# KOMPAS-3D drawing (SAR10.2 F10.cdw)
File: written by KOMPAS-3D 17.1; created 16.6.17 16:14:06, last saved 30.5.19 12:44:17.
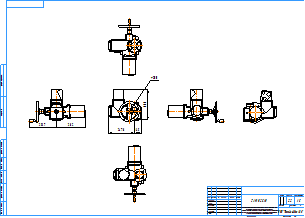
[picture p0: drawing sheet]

Sheet 1: A2, landscape

Title block, sheet 1: name: SAR10.2 F10; material: Сталь 20  ГОСТ 1050-88; mass: 22; sheets: 1; sheet format: A2; stored path: \\adlc.lan\data\АДЛ_ПКД\3D-модели\Поставщики\Сервоприводы AUMA\Электроприводы серии SA\KOMPAS 2D\SA 10.2 F10.cdw

Views: Спереди 1, Проекционный вид 3, Проекционный вид 4, Проекционный вид 6, Проекционный вид 5, Проекционный вид 2
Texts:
  Klimkovich
  ADL
  Рама для чертежей
  Лит-Масса-Масштаб
  Материал-Предприятие
  Масштаб
  Изм.
  Лист
  № докум.
  Подп.
  Дата
  Лит.
  Разраб.
  Пров.
  Т.контр.
  Листов
  Внимание! Данный продукт является объектом авторского права ООО «Торговый Дом АДЛ».
  Запрещается изменение, копирование, распространение
  (в том числе путем копирования на другие сайты и ресурсы в Интернете)
  или любое иное использование информации и объектов без предварительного
  согласия правообладателя (ООО «Торговый Дом АДЛ»).
  Н.контр.
  Утв.
  ООО "Торговый дом АДЛ"
  Изменение
  Номер документа
  Подпись
  Обозначение документа
  Наименование изделия
  Масса изделия по ГОСТ 2.109-73
  Порядковый номер листа
  Общее количество листов в документе
  Характер работы, выполненной лицом, подписавшим документ
  Наименование или индекс предприятия, выпускающего документ
  Инв. № подл.
  Подп. и дата
  Взам. инв. №
  Инв. № дубл.
  Инвентарный номер подлинника по ГОСТ 2.501-68
  Подпись принявшего подлинник в отдел технической документации
  Инвентарный номер подлинника, взамен которого выпущен данный подлинник
  Инвентарный номер дубликата по ГОСТ 2.502-68
  Подпись принявшего дубликат в отдел технической документации
  Справ. №
  Перв. примен.
  Обозначение документа, взамен или на основании которого выпущен данный документ
  Обозначение документа, в котором впервые записан данный документ
  Подпись лица, копировавшего чертеж
  Обозначение формата листа
  !Рама для чертежа
Dimensions and other numbers on the sheet: 200; 290; 247,8; 65; 253,7; 282; 1:5; 1; 22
